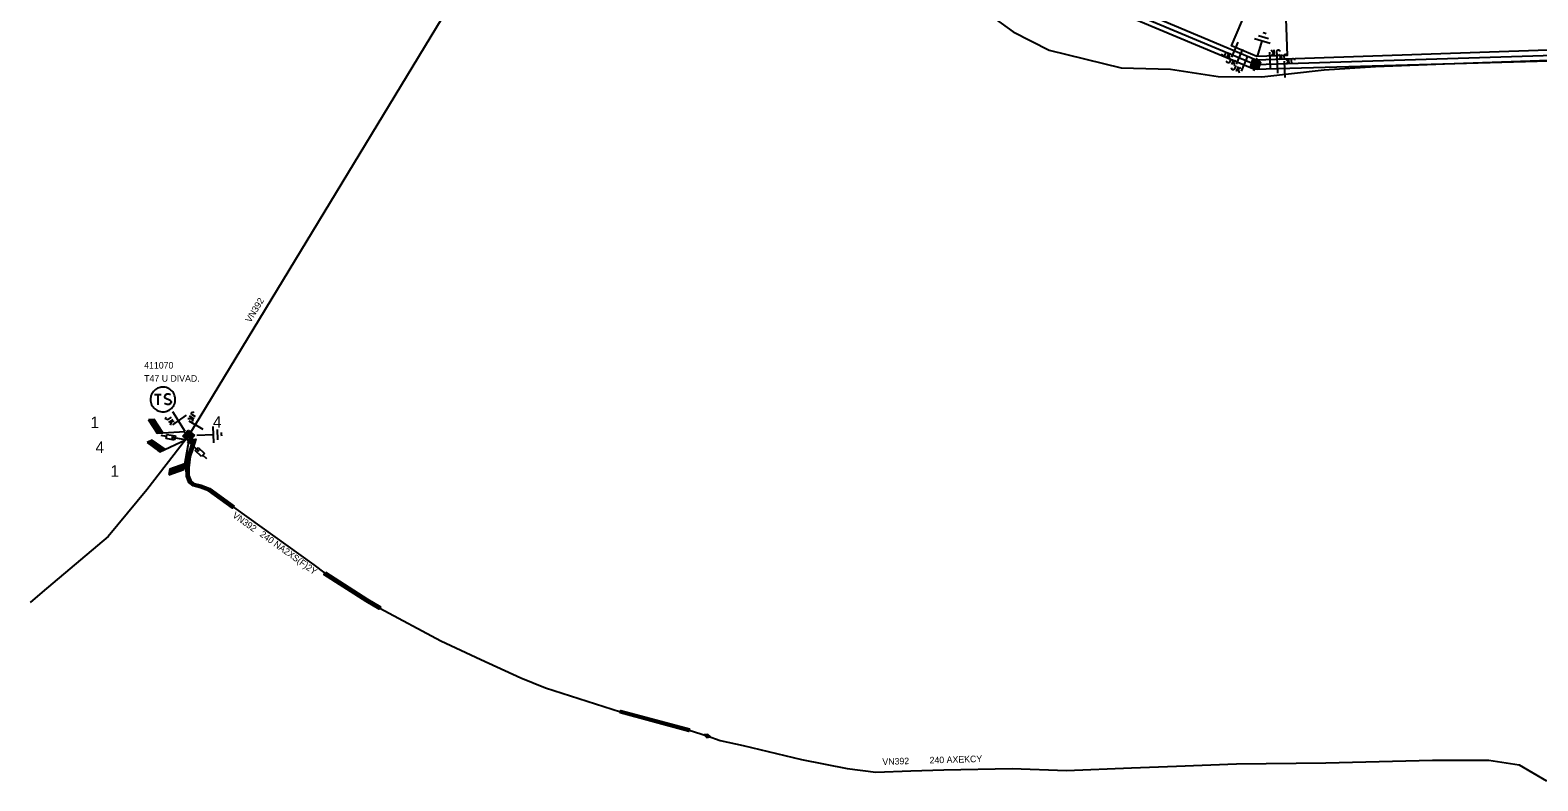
# Model space of a CAD drawing. Extents: x -540340 to -537226, y -1183949 to -1180375.
# Drawn here: x -537651.5 to -537421.3, y -1180804.6 to -1180690 of the extents above; entities that cross this region are included whole.
import ezdxf

# ---------------------------------------------------------------- set-up
doc = ezdxf.new("R2010")
doc.units = 0
for name, color, linetype in [('Vrstva 1', 7, 'Continuous'), ('Vrstva 11', 7, 'Continuous'), ('Vrstva 12', 7, 'Continuous'), ('Vrstva 13', 7, 'Continuous'), ('Vrstva 14', 7, 'Continuous'), ('Vrstva 15', 7, 'Continuous'), ('Vrstva 16', 7, 'Continuous'), ('Vrstva 18', 7, 'Continuous'), ('Vrstva 19', 7, 'Continuous'), ('Vrstva 20', 7, 'Continuous'), ('Vrstva 25', 7, 'Continuous'), ('Vrstva 26', 7, 'Continuous'), ('Vrstva 27', 7, 'Continuous'), ('Vrstva 3', 7, 'Continuous'), ('Vrstva 35', 7, 'Continuous'), ('Vrstva 4', 7, 'Continuous'), ('Vrstva 5', 7, 'Continuous'), ('Vrstva 6', 7, 'Continuous'), ('Vrstva 7', 7, 'Continuous')]:
    doc.layers.add(name, color=color, linetype=linetype)

msp = doc.modelspace()

# ---------------------------------------------------------------- linework, layer by layer
at = {"layer": 'Vrstva 1'}
for points in [[(-537531.99, -1180665.41), (-537572.36, -1180661.38), (-537627.26, -1180751.9)], [(-537513.97, -1180675.24), (-537464.53, -1180695.92), (-537378.21, -1180693.51), (-537311.07, -1180690.92), (-537228.83, -1180686.56)], [(-537512.82, -1180674.92), (-537464.4, -1180695.21), (-537378.15, -1180692.5), (-537311.07, -1180689.98), (-537229.16, -1180685.67)], [(-537511.59, -1180674.55), (-537464.27, -1180694.51), (-537378.16, -1180691.54), (-537311.24, -1180689.01), (-537229.49, -1180684.77)]]:
    msp.add_lwpolyline(points, dxfattribs=at)
at = {"layer": 'Vrstva 11'}
for p, q in [((-537632, -1180751.49), (-537633.32, -1180749.47)), ((-537631.94, -1180751.49), (-537633.26, -1180749.47)), ((-537631.89, -1180751.49), (-537633.2, -1180749.46)), ((-537631.83, -1180751.48), (-537633.15, -1180749.46)), ((-537631.77, -1180751.48), (-537633.09, -1180749.46)), ((-537631.71, -1180751.48), (-537633.03, -1180749.45)), ((-537631.66, -1180751.47), (-537632.97, -1180749.45)), ((-537631.6, -1180751.47), (-537632.92, -1180749.45)), ((-537631.54, -1180751.47), (-537632.86, -1180749.44)), ((-537631.48, -1180751.46), (-537632.8, -1180749.44)), ((-537631.43, -1180751.46), (-537632.74, -1180749.44)), ((-537631.37, -1180751.46), (-537632.69, -1180749.43)), ((-537631.31, -1180751.45), (-537632.63, -1180749.43)), ((-537631.25, -1180751.45), (-537632.57, -1180749.43)), ((-537632.06, -1180751.5), (-537632.28, -1180751.15)), ((-537631.58, -1180754.32), (-537633.56, -1180752.92)), ((-537631.53, -1180754.29), (-537633.5, -1180752.9)), ((-537631.48, -1180754.27), (-537633.45, -1180752.87)), ((-537631.43, -1180754.24), (-537633.4, -1180752.85)), ((-537631.37, -1180754.22), (-537633.35, -1180752.83)), ((-537631.32, -1180754.2), (-537633.29, -1180752.8)), ((-537631.27, -1180754.17), (-537633.24, -1180752.78)), ((-537631.22, -1180754.15), (-537633.19, -1180752.75)), ((-537631.17, -1180754.12), (-537633.14, -1180752.73)), ((-537631.11, -1180754.1), (-537633.08, -1180752.7)), ((-537631.06, -1180754.07), (-537633.03, -1180752.68)), ((-537631.01, -1180754.05), (-537632.98, -1180752.66)), ((-537630.96, -1180754.02), (-537632.93, -1180752.63)), ((-537630.91, -1180754), (-537632.87, -1180752.61)), ((-537631.64, -1180754.34), (-537631.97, -1180754.1)), ((-537627.99, -1180757), (-537630.26, -1180757.81)), ((-537627.98, -1180756.94), (-537630.25, -1180757.75)), ((-537627.97, -1180756.89), (-537630.24, -1180757.7)), ((-537627.96, -1180756.83), (-537630.23, -1180757.64)), ((-537627.95, -1180756.77), (-537630.22, -1180757.58)), ((-537627.94, -1180756.72), (-537630.21, -1180757.53)), ((-537627.93, -1180756.66), (-537630.2, -1180757.47)), ((-537627.92, -1180756.6), (-537630.19, -1180757.41)), ((-537627.91, -1180756.55), (-537630.18, -1180757.35)), ((-537627.89, -1180756.49), (-537630.17, -1180757.3)), ((-537627.88, -1180756.43), (-537630.16, -1180757.24)), ((-537627.87, -1180756.38), (-537630.15, -1180757.18)), ((-537627.86, -1180756.32), (-537630.14, -1180757.13)), ((-537627.85, -1180756.26), (-537630.13, -1180757.07)), ((-537628, -1180757.06), (-537628.38, -1180757.19))]:
    msp.add_line(p, q, dxfattribs=at)
for points in [[(-537633.37, -1180749.47), (-537632.06, -1180751.5), (-537631.2, -1180751.45), (-537632.52, -1180749.42)], [(-537633.6, -1180752.94), (-537631.64, -1180754.34), (-537630.86, -1180753.98), (-537632.83, -1180752.59)], [(-537630.27, -1180757.86), (-537628, -1180757.06), (-537627.84, -1180756.21), (-537630.12, -1180757.02)]]:
    msp.add_lwpolyline(points, close=True, dxfattribs=at)
for points in [[(-537632.06, -1180751.5), (-537627.77, -1180751.25)], [(-537631.64, -1180754.34), (-537627.74, -1180752.52)], [(-537628, -1180757.06), (-537627.24, -1180752.83)]]:
    msp.add_lwpolyline(points, dxfattribs=at)
at = {"layer": 'Vrstva 13'}
for points in [[(-537465.16, -1180695.64), (-537464.82, -1180694.46)], [(-537464.97, -1180695.54), (-537464.72, -1180694.66)], [(-537464.82, -1180694.46), (-537463.64, -1180694.79)], [(-537464.78, -1180695.43), (-537464.61, -1180694.84)], [(-537464.72, -1180694.66), (-537463.83, -1180694.91)], [(-537464.61, -1180694.84), (-537464.02, -1180695)], [(-537464.23, -1180694.62), (-537464.13, -1180694.26)], [(-537463.83, -1180694.91), (-537464.08, -1180695.79)], [(-537463.64, -1180694.79), (-537463.98, -1180695.97)], [(-537463.98, -1180695.97), (-537465.16, -1180695.64)], [(-537464.08, -1180695.79), (-537464.97, -1180695.54)], [(-537464.19, -1180695.59), (-537464.78, -1180695.43)], [(-537464.57, -1180695.81), (-537464.67, -1180696.17)], [(-537464.58, -1180695.3), (-537464.5, -1180695.01)], [(-537464.29, -1180695.39), (-537464.58, -1180695.3)], [(-537464.5, -1180695.01), (-537464.2, -1180695.09)], [(-537464.2, -1180695.09), (-537464.29, -1180695.39)], [(-537464.02, -1180695), (-537464.19, -1180695.59)], [(-537628.13, -1180751.96), (-537627.32, -1180751.03)], [(-537627.21, -1180752.77), (-537628.13, -1180751.96)], [(-537627.72, -1180751.49), (-537628, -1180751.25)], [(-537627.9, -1180751.95), (-537627.29, -1180751.26)], [(-537627.21, -1180752.56), (-537627.9, -1180751.95)], [(-537627.69, -1180751.93), (-537627.29, -1180751.47)], [(-537627.23, -1180752.33), (-537627.69, -1180751.93)], [(-537627.49, -1180751.9), (-537627.29, -1180751.67)], [(-537627.26, -1180752.11), (-537627.49, -1180751.9)], [(-537627.32, -1180751.03), (-537626.39, -1180751.85)], [(-537627.29, -1180751.26), (-537626.6, -1180751.87)], [(-537627.29, -1180751.47), (-537626.83, -1180751.87)], [(-537627.29, -1180751.67), (-537627.06, -1180751.87)], [(-537627.06, -1180751.87), (-537627.26, -1180752.11)], [(-537626.83, -1180751.87), (-537627.23, -1180752.33)], [(-537626.39, -1180751.85), (-537627.21, -1180752.77)], [(-537626.6, -1180751.87), (-537627.21, -1180752.56)], [(-537626.8, -1180752.31), (-537626.52, -1180752.55)]]:
    msp.add_lwpolyline(points, dxfattribs=at)
at = {"layer": 'Vrstva 15'}
for points in [[(-537463.27, -1180690.34), (-537463.02, -1180690.41)], [(-537464.56, -1180691.26), (-537462.16, -1180691.96)], [(-537464.06, -1180694.01), (-537463.36, -1180691.61)], [(-537463.93, -1180690.8), (-537462.42, -1180691.24)], [(-537463.02, -1180690.41), (-537462.77, -1180690.48)], [(-537626.02, -1180751.84), (-537623.52, -1180751.74)], [(-537623.57, -1180750.49), (-537623.47, -1180752.99)], [(-537622.93, -1180750.95), (-537622.87, -1180752.52)], [(-537622.28, -1180751.42), (-537622.27, -1180751.69)], [(-537622.27, -1180751.69), (-537622.26, -1180751.94)]]:
    msp.add_lwpolyline(points, dxfattribs=at)
at = {"layer": 'Vrstva 16'}
for points in [[(-537630.65, -1180752.02), (-537631.43, -1180751.88)], [(-537630.71, -1180752.35), (-537630.59, -1180751.7)], [(-537629.41, -1180752.57), (-537630.71, -1180752.35)], [(-537630.59, -1180751.7), (-537629.29, -1180751.93)], [(-537629.82, -1180752.16), (-537629.55, -1180752.09)], [(-537627.74, -1180752.53), (-537629.82, -1180752.16)], [(-537629.82, -1180752.16), (-537629.59, -1180752.32)], [(-537629.29, -1180751.93), (-537629.41, -1180752.57)], [(-537627.24, -1180752.82), (-537625.71, -1180754.27)], [(-537626.27, -1180754.18), (-537625.82, -1180753.7)], [(-537625.32, -1180755.09), (-537626.27, -1180754.18)], [(-537625.71, -1180754.27), (-537625.97, -1180754.19)], [(-537625.82, -1180753.7), (-537624.86, -1180754.61)], [(-537625.71, -1180754.27), (-537625.8, -1180754.02)], [(-537624.86, -1180754.61), (-537625.32, -1180755.09)], [(-537625.09, -1180754.85), (-537624.51, -1180755.4)]]:
    msp.add_lwpolyline(points, dxfattribs=at)
at = {"layer": 'Vrstva 18'}
for points in [[(-537467.08, -1180691.8), (-537468.05, -1180694.1)], [(-537469.5, -1180693.78), (-537469.49, -1180693.67)], [(-537469.39, -1180693.9), (-537469.5, -1180693.78)], [(-537469.49, -1180693.67), (-537469.45, -1180693.58)], [(-537469.34, -1180693.92), (-537469.39, -1180693.9)], [(-537469.18, -1180693.91), (-537469.34, -1180693.92)], [(-537469.11, -1180693.83), (-537469.18, -1180693.91)], [(-537468.86, -1180693.23), (-537469.11, -1180693.83)], [(-537468.47, -1180693.39), (-537468.79, -1180694.15)], [(-537468.77, -1180694.85), (-537468.76, -1180694.73)], [(-537468.66, -1180694.97), (-537468.77, -1180694.85)], [(-537468.76, -1180694.73), (-537468.72, -1180694.64)], [(-537468.67, -1180693.86), (-537468.09, -1180693.55)], [(-537468.61, -1180694.99), (-537468.66, -1180694.97)], [(-537468.45, -1180694.98), (-537468.61, -1180694.99)], [(-537468.48, -1180693.76), (-537468.35, -1180694.34)], [(-537468.38, -1180694.89), (-537468.45, -1180694.98)], [(-537468.13, -1180694.29), (-537468.38, -1180694.89)], [(-537467.74, -1180694.45), (-537468.06, -1180695.22)], [(-537467.94, -1180694.93), (-537467.36, -1180694.61)], [(-537467.75, -1180694.83), (-537467.62, -1180695.4)], [(-537466.35, -1180692.86), (-537467.32, -1180695.17)], [(-537465.62, -1180693.93), (-537466.58, -1180696.23)], [(-537462.12, -1180695.86), (-537462.19, -1180693.36)], [(-537461.66, -1180693.49), (-537462.02, -1180693.02)], [(-537461.53, -1180693.32), (-537461.92, -1180693.84)], [(-537461.51, -1180693.83), (-537461.54, -1180693)], [(-537461.12, -1180693.17), (-537461.08, -1180693.06)], [(-537461.1, -1180693.82), (-537461.12, -1180693.17)], [(-537461.08, -1180693.06), (-537460.95, -1180692.98)], [(-537461, -1180696.52), (-537461.08, -1180694.02)], [(-537460.95, -1180692.98), (-537460.89, -1180692.98)], [(-537460.54, -1180694.15), (-537460.9, -1180693.68)], [(-537460.89, -1180692.98), (-537460.74, -1180693.05)], [(-537460.41, -1180693.98), (-537460.81, -1180694.51)], [(-537460.74, -1180693.05), (-537460.7, -1180693.15)], [(-537460.7, -1180693.15), (-537460.7, -1180693.25)], [(-537460.39, -1180694.49), (-537460.42, -1180693.67)], [(-537460, -1180693.83), (-537459.96, -1180693.72)], [(-537459.98, -1180694.48), (-537460, -1180693.83)], [(-537459.96, -1180693.72), (-537459.83, -1180693.65)], [(-537459.87, -1180697.18), (-537459.94, -1180694.69)], [(-537459.83, -1180693.65), (-537459.77, -1180693.65)], [(-537459.77, -1180693.65), (-537459.62, -1180693.71)], [(-537459.41, -1180694.82), (-537459.77, -1180694.35)], [(-537459.28, -1180694.65), (-537459.67, -1180695.17)], [(-537459.62, -1180693.71), (-537459.59, -1180693.82)], [(-537459.59, -1180693.82), (-537459.58, -1180693.92)], [(-537459.26, -1180695.16), (-537459.29, -1180694.33)], [(-537458.87, -1180694.49), (-537458.83, -1180694.39)], [(-537458.85, -1180695.14), (-537458.87, -1180694.49)], [(-537458.83, -1180694.39), (-537458.7, -1180694.31)], [(-537458.7, -1180694.31), (-537458.64, -1180694.31)], [(-537458.64, -1180694.31), (-537458.49, -1180694.37)], [(-537458.49, -1180694.37), (-537458.45, -1180694.48)], [(-537458.45, -1180694.48), (-537458.45, -1180694.58)], [(-537468.04, -1180695.91), (-537468.02, -1180695.8)], [(-537467.93, -1180696.03), (-537468.04, -1180695.91)], [(-537468.02, -1180695.8), (-537467.99, -1180695.71)], [(-537467.88, -1180696.05), (-537467.93, -1180696.03)], [(-537467.72, -1180696.04), (-537467.88, -1180696.05)], [(-537467.64, -1180695.96), (-537467.72, -1180696.04)], [(-537467.39, -1180695.36), (-537467.64, -1180695.96)], [(-537467.01, -1180695.52), (-537467.33, -1180696.28)], [(-537467.21, -1180695.99), (-537466.63, -1180695.68)], [(-537467.02, -1180695.89), (-537466.89, -1180696.47)], [(-537630.77, -1180749.2), (-537630.7, -1180749.11)], [(-537630.74, -1180749.36), (-537630.77, -1180749.2)], [(-537630.7, -1180749.4), (-537630.74, -1180749.36)], [(-537630.7, -1180749.11), (-537630.62, -1180749.05)], [(-537630.57, -1180749.48), (-537630.7, -1180749.4)], [(-537630.46, -1180749.45), (-537630.57, -1180749.48)], [(-537629.93, -1180749.07), (-537630.46, -1180749.45)], [(-537629.69, -1180749.41), (-537630.36, -1180749.89)], [(-537630.1, -1180749.7), (-537629.45, -1180749.74)], [(-537629.89, -1180749.72), (-537630.08, -1180750.28)], [(-537627.66, -1180748.79), (-537629.7, -1180750.24)], [(-537626.78, -1180749.3), (-537627.37, -1180749.34)], [(-537625.04, -1180750.97), (-537627.18, -1180749.67)], [(-537626.41, -1180749.36), (-537627.12, -1180748.93)], [(-537626.85, -1180749.09), (-537626.63, -1180749.71)], [(-537626.83, -1180748.58), (-537626.82, -1180748.42)], [(-537626.76, -1180748.67), (-537626.83, -1180748.58)], [(-537626.82, -1180748.42), (-537626.78, -1180748.37)], [(-537626.78, -1180748.37), (-537626.65, -1180748.28)], [(-537626.2, -1180749), (-537626.76, -1180748.67)], [(-537626.65, -1180748.28), (-537626.54, -1180748.31)], [(-537626.54, -1180748.31), (-537626.46, -1180748.36)]]:
    msp.add_lwpolyline(points, dxfattribs=at)
at = {"layer": 'Vrstva 19'}
for points in [[(-537627.42, -1180752.92), (-537626.76, -1180752.28)], [(-537626.61, -1180752.99), (-537627.28, -1180752.87), (-537626.79, -1180752.41), (-537626.61, -1180752.99)], [(-537626.72, -1180752.91), (-537627.13, -1180752.82), (-537626.83, -1180752.54), (-537626.72, -1180752.91)], [(-537626.76, -1180752.28), (-537626.52, -1180753.06)], [(-537626.52, -1180753.06), (-537627.42, -1180752.92)], [(-537626.82, -1180752.82), (-537626.99, -1180752.78), (-537626.87, -1180752.66), (-537626.82, -1180752.82)], [(-537626.88, -1180752.74), (-537626.87, -1180752.77), (-537626.9, -1180752.76), (-537626.88, -1180752.74)], [(-537548.01, -1180797.5), (-537548.56, -1180797.59), (-537548.15, -1180797.98), (-537547.6, -1180797.89), (-537548.01, -1180797.5)], [(-537548.43, -1180797.63), (-537548.14, -1180797.92), (-537547.74, -1180797.85), (-537548.02, -1180797.56), (-537548.43, -1180797.63)], [(-537548.31, -1180797.66), (-537548.12, -1180797.86), (-537547.84, -1180797.81), (-537548.04, -1180797.62), (-537548.31, -1180797.66)], [(-537548.2, -1180797.7), (-537548.1, -1180797.8), (-537547.96, -1180797.78), (-537548.06, -1180797.68), (-537548.2, -1180797.7)]]:
    msp.add_lwpolyline(points, dxfattribs=at)
at = {"layer": 'Vrstva 20'}
for points in [[(-537620.3, -1180762.65), (-537620.54, -1180762.97), (-537624.25, -1180760.33), (-537625.47, -1180759.84), (-537626.58, -1180759.57), (-537627.23, -1180759.03), (-537627.61, -1180758.06), (-537627.63, -1180756.79), (-537627.39, -1180754.96), (-537627, -1180753.8), (-537626.74, -1180752.95), (-537627.21, -1180753.02), (-537627.27, -1180752.63), (-537626.18, -1180752.45), (-537626.62, -1180753.92), (-537627.01, -1180755.08), (-537627.23, -1180756.83), (-537627.21, -1180757.98), (-537626.91, -1180758.75), (-537626.44, -1180759.19), (-537625.35, -1180759.46), (-537624.05, -1180759.97)], [(-537606.38, -1180772.73), (-537599.95, -1180776.87), (-537597.95, -1180778.04), (-537598.15, -1180778.38), (-537600.15, -1180777.21), (-537606.6, -1180773.07)], [(-537550.82, -1180796.68), (-537550.92, -1180797.06), (-537561.36, -1180794.23), (-537561.26, -1180793.85)]]:
    msp.add_lwpolyline(points, close=True, dxfattribs=at)
at = {"layer": 'Vrstva 25'}
for points in [[(-537629.31, -1180746.32), (-537629.32, -1180746.13), (-537629.36, -1180745.93), (-537629.41, -1180745.74), (-537629.49, -1180745.56), (-537629.58, -1180745.38), (-537629.69, -1180745.22), (-537629.82, -1180745.07), (-537629.96, -1180744.93), (-537630.12, -1180744.81), (-537630.29, -1180744.71), (-537630.46, -1180744.62), (-537630.65, -1180744.55), (-537630.84, -1180744.51), (-537631.04, -1180744.48), (-537631.24, -1180744.47), (-537631.43, -1180744.49), (-537631.63, -1180744.52), (-537631.82, -1180744.58), (-537632, -1180744.65), (-537632.18, -1180744.75), (-537632.34, -1180744.86), (-537632.49, -1180744.99), (-537632.63, -1180745.13), (-537632.75, -1180745.29), (-537632.85, -1180745.45), (-537632.94, -1180745.63), (-537633.01, -1180745.82), (-537633.05, -1180746.01), (-537633.08, -1180746.21), (-537633.09, -1180746.4), (-537633.07, -1180746.6), (-537633.04, -1180746.8), (-537632.98, -1180746.99), (-537632.91, -1180747.17), (-537632.81, -1180747.34), (-537632.7, -1180747.51), (-537632.57, -1180747.66), (-537632.43, -1180747.79), (-537632.27, -1180747.92), (-537632.11, -1180748.02), (-537631.93, -1180748.11), (-537631.74, -1180748.17), (-537631.55, -1180748.22), (-537631.35, -1180748.25), (-537631.16, -1180748.25), (-537630.96, -1180748.24), (-537630.76, -1180748.2), (-537630.57, -1180748.15), (-537630.39, -1180748.07), (-537630.22, -1180747.98), (-537630.05, -1180747.87), (-537629.9, -1180747.74), (-537629.77, -1180747.6), (-537629.64, -1180747.44), (-537629.54, -1180747.27), (-537629.45, -1180747.09), (-537629.39, -1180746.91), (-537629.34, -1180746.72), (-537629.31, -1180746.52), (-537629.31, -1180746.32)], [(-537632.47, -1180745.61), (-537631.47, -1180745.59)], [(-537631.97, -1180745.6), (-537631.94, -1180747.17)], [(-537630.01, -1180745.68), (-537630.27, -1180745.56), (-537630.58, -1180745.57), (-537630.83, -1180745.7), (-537630.96, -1180745.89), (-537630.95, -1180745.95), (-537630.82, -1180746.14), (-537630.06, -1180746.5), (-537629.93, -1180746.66), (-537629.93, -1180746.81), (-537630.05, -1180747), (-537630.3, -1180747.14), (-537630.55, -1180747.14), (-537630.68, -1180747.08), (-537630.93, -1180746.96)]]:
    msp.add_lwpolyline(points, dxfattribs=at)
at = {"layer": 'Vrstva 35'}
msp.add_lwpolyline([(-537464.75, -1180684.54), (-537462.6, -1180685.45), (-537459.87, -1180685.35), (-537459.57, -1180693.85), (-537464.18, -1180694.01), (-537468.05, -1180692.37)], close=True, dxfattribs=at)
at = {"layer": 'Vrstva 4'}
msp.add_lwpolyline([(-537627.77, -1180751.25), (-537629.68, -1180748.25)], dxfattribs=at)
at = {"layer": 'Vrstva 5'}
for points in [[(-537530.88, -1180661.78), (-537532.37, -1180661.32), (-537533.38, -1180662.14), (-537534.59, -1180663.75), (-537534.3, -1180664.46), (-537528.92, -1180669.15), (-537521.77, -1180675.43), (-537512.81, -1180681.59), (-537510, -1180683.99), (-537501.37, -1180690.23), (-537495.9, -1180693.02), (-537484.88, -1180695.74), (-537477.36, -1180695.95), (-537470.1, -1180697.06), (-537463.41, -1180697.1), (-537453.89, -1180696.05), (-537446.06, -1180695.54), (-537435.56, -1180695.14), (-537412.34, -1180694.31)], [(-537627.74, -1180752.53), (-537633.63, -1180760.19), (-537639.56, -1180767.3), (-537649.64, -1180775.77), (-537651.46, -1180777.38)], [(-537627.24, -1180752.83), (-537626.46, -1180752.7), (-537626.81, -1180753.86), (-537627.2, -1180755.02), (-537627.44, -1180756.77), (-537627.41, -1180758.02), (-537627.07, -1180758.89), (-537626.51, -1180759.38), (-537625.41, -1180759.65), (-537624.15, -1180760.15), (-537620.42, -1180762.81), (-537608.16, -1180771.64), (-537606.49, -1180772.9), (-537600.05, -1180777.04), (-537598.05, -1180778.21), (-537588.76, -1180783.22), (-537582.64, -1180786.05), (-537576.54, -1180788.86), (-537572.76, -1180790.42), (-537561.31, -1180794.04), (-537550.87, -1180796.87), (-537548.08, -1180797.74)], [(-537548.08, -1180797.74), (-537546.12, -1180798.45), (-537542.6, -1180799.18), (-537533.71, -1180801.34), (-537526.71, -1180802.71), (-537522.37, -1180803.27), (-537517.01, -1180803.08), (-537511.95, -1180802.94), (-537501.55, -1180802.72), (-537493.24, -1180803.04), (-537483.34, -1180802.6), (-537476.44, -1180802.37), (-537467.3, -1180802), (-537453.64, -1180801.86), (-537437.37, -1180801.42), (-537428.75, -1180801.44), (-537424.15, -1180802.18), (-537419.95, -1180804.6)]]:
    msp.add_lwpolyline(points, dxfattribs=at)

# ---------------------------------------------------------------- texts
at = {"layer": 'Vrstva 12'}
for s, p in [('1', (-537642.26, -1180750.75)), ('4', (-537641.47, -1180754.53)), ('1', (-537639.2, -1180758.17))]:
    msp.add_text(s, height=1.75, dxfattribs=at).set_placement(p)
at = {"layer": 'Vrstva 14'}
msp.add_text('4', height=1.75, dxfattribs=at).set_placement((-537623.54, -1180750.67))
at = {"layer": 'Vrstva 26'}
msp.add_text('411070', height=1, dxfattribs=at).set_placement((-537634.05, -1180741.65))
at = {"layer": 'Vrstva 27'}
msp.add_text('T47 U DIVAD.', height=1, dxfattribs=at).set_placement((-537634.05, -1180743.65))
at = {"layer": 'Vrstva 3'}
msp.add_text('VN392', height=1, rotation=58.763, dxfattribs=at).set_placement((-537617.81, -1180734.72))
at = {"layer": 'Vrstva 6'}
for s, rotation, p in [('240 NA2XS(F)2Y', 324.237, (-537616.49, -1180767.16)), ('240 AXEKCY', 1.617, (-537514.13, -1180801.95))]:
    msp.add_text(s, height=1, rotation=rotation, dxfattribs=at).set_placement(p)
at = {"layer": 'Vrstva 7'}
for rotation, p in [(324.237, (-537620.66, -1180764.26)), (2.041, (-537521.33, -1180802.19))]:
    msp.add_text('VN392', height=1, rotation=rotation, dxfattribs=at).set_placement(p)

doc.saveas('drawing.dxf')
